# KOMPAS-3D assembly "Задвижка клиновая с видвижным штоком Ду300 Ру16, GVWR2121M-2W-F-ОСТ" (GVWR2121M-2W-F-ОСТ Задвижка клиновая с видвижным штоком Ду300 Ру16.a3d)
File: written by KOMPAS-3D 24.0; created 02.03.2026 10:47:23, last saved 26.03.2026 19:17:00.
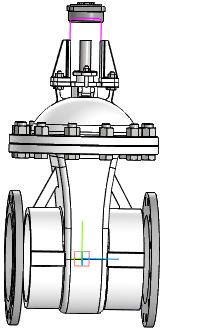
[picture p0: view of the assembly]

Document properties: Автор: R2D2; Полное имя файла: E:\Работа\Зайцев\GVWR2121M-2W-F-ОСТ Задвижка клиновая с видвижным штоком Ду50-300 Ру16\DN300\Исходные материалы\GVWR2121M-2W-F-ОСТ Задвижка клиновая с видвижным штоком Ду300 Ру16.a3d

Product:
- Component [detail]: AS 1110 - M10 x 35  | qty 4  | pos. 2  | Масса: 0.110391; Комментарий: Болты и винты   шестигранные точные   метрические ISO; Автор: R2D2; additional columns: Сталь, мягкая; source file: AS 1110 - M10 x 35 AS 1110 - M10 x 35.m3d
- Component [detail]: ANSI B18.2.4.2M - M10x1,5 - 16  | designation ANSI B18.2.4.2M - M10x1,5  | qty 4  | pos. 3  | Масса: 0.040912; Комментарий: Типы метрических   шестигранных гаек   2; Автор: R2D2; additional columns: Сталь, мягкая; source file: ANSI B18.2.4.2M - M10x1,5 ANSI B18.2.4.2M - M10x1,5 - 16.m3d
- Component [detail]: ANSI B18.2.4.2M - M8x1,25 - 13  | designation ANSI B18.2.4.2M - M8x1,25  | qty 1  | pos. 4  | Масса: 0.022147; Комментарий: Типы метрических   шестигранных гаек   2; Автор: R2D2; additional columns: Сталь, мягкая; source file: ANSI B18.2.4.2M - M8x1,25 ANSI B18.2.4.2M - M8x1,25 - 13.m3d
- Component [detail]: ANSI B18.2.4.2M - M20x2,5 - 30  | designation ANSI B18.2.4.2M - M20x2,5  | qty 12  | pos. 5  | Масса: 0.285661; Комментарий: Типы метрических   шестигранных гаек   2; Автор: R2D2; additional columns: Сталь, мягкая; source file: ANSI B18.2.4.2M - M20x2,5 ANSI B18.2.4.2M - M20x2,5 - 30.m3d
- Component [detail]: AS 1110 - M20 x 70  | qty 12  | pos. 6  | Масса: 0.838149; Комментарий: Болты и винты   шестигранные точные   метрические ISO; Автор: R2D2; additional columns: Сталь, мягкая; source file: AS 1110 - M20 x 70 AS 1110 - M20 x 70.m3d
- Component [detail]: Деталь1  | qty 1  | pos. 7  | Масса: 456.890978; Автор: R2D2; additional columns: Типовые; source file: 2.m3d
- Component [detail]: ANSI B18.2.4.2M - M8x1,25 - 13  | designation ANSI B18.2.4.2M - M8x1,25-01  | qty 1  | pos. 8  | Масса: 0.022147; Комментарий: Типы метрических   шестигранных гаек   2; Автор: R2D2; additional columns: Сталь, мягкая; source file: ANSI B18.2.4.2M - M8x1,25 ANSI B18.2.4.2M - M8x1,25 - 13.m3d
- Component [detail]: Фланец  | qty 2  | pos. 7  | Масса: 20.137324; Автор: R2D2; additional columns: Типовые; source file: Фланец DN300 Pn16 b31.m3d
- Component [assembly]: DN250_3D_STEP  | designation Сборка  | qty 1  | pos. 9  | Масса: 5.389074; Автор: R2D2; source file: Фланец Б.a3d
- Part/product: Задвижка клиновая с видвижным штоком Ду300 Ру16  | designation GVWR2121M-2W-F-ОСТ
    Масса: 210
    Раздел спецификации: Прочие изделия
    Примечание: D040-07880

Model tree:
1. Массив по концентрической сетке:1  (labels: Грань.Твердое тело1)  (12 pattern instances)
     Шаг 2 = 360
2. Массив по сетке:1  (labels: Грань.Твердое тело1)  (4 pattern instances)
     Шаг 1 = 50; Угол раствора = 90; Шаг 2 = 120
3. Масштабирование:1
4. Масштабирование : Твердое тело1
5. Масштабирование : Solid1  (labels: Твердое тело1; Solid1)
     Масштаб по оси Х = 1; Масштаб по оси Y = 1; Масштаб по оси Z = 1; Коэффициент = 1.5
6. Эскиз:1  (with: Вершина.Элемент выдавливания:2, Грань.Элемент вращения:1, Грань.Элемент выдавливания:5, Грань.Элемент выдавливания:7)  (labels: Грань.Твердое тело1; Грань.Solid1; Solid1; Твердое тело1)
     Ориентация = 2; Расстояние = -250; Ориентация = 2; Расстояние = -876

Referenced files in E:\Работа\Зайцев\GVWR2121M-2W-F-ОСТ Задвижка клиновая с видвижным штоком Ду50-300 Ру16\DN300\Исходные материалы\: AS 1110 - M10 x 35 AS 1110 - M10 x 35.m3d, ANSI B18.2.4.2M - M10x1,5 ANSI B18.2.4.2M - M10x1,5 - 16.m3d, ANSI B18.2.4.2M - M8x1,25 ANSI B18.2.4.2M - M8x1,25 - 13.m3d, ANSI B18.2.4.2M - M20x2,5 ANSI B18.2.4.2M - M20x2,5 - 30.m3d, AS 1110 - M20 x 70 AS 1110 - M20 x 70.m3d, 2.m3d, Фланец DN300 Pn16 b31.m3d, Фланец Б.a3d
Referenced files in E:\Работа\Зайцев\GVWR3131M-2W-F-S Задвижка клиновая с выдвижным штоком DN.ru Ду50-200 Ру63\DN200\исходные материалы\: ANSI B18.2.4.2M - M20x2,5 ANSI B18.2.4.2M - M20x2,5 - 30.m3d, AS 1110 - M20 x 70 AS 1110 - M20 x 70.m3d, ANSI B18.2.4.2M - M10x1,5 ANSI B18.2.4.2M - M10x1,5 - 16.m3d, AS 1110 - M10 x 35 AS 1110 - M10 x 35.m3d
Referenced files in E:\Работа\Зайцев\GVWR2626M-2W-F-S Задвижка клиновая с выдвижным штоком DN.ru Ду50-300 Ру16\DN300\исходные материалы\: Фланец DN300 Pn16 b31.m3d
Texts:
  Программные изделия  и базы данных
  ANSI B18.2.4.2M - M10x1,5
  ANSI B18.2.4.2M - M8x1,25
  ANSI B18.2.4.2M - M20x2,5
  ANSI B18.2.4.2M - M8x1,25 - 01
  ANSI B18.2.4.2M - M8x1,25-01
  GVWR2121M-2W-F-ОСТ
  AS 1110 - M10 x 35 AS 1110 - M10 x 35 (1)
  ANSI B18.2.4.2M - M10x1,5 ANSI B18.2.4.2M - M10x1,5 - 16 (1)
  ANSI B18.2.4.2M - M8x1,25 ANSI B18.2.4.2M - M8x1,25 - 13
  ANSI B18.2.4.2M - M20x2,5 ANSI B18.2.4.2M - M20x2,5 - 30 (1)
  AS 1110 - M20 x 70 AS 1110 - M20 x 70 (1)
  Деталь1 Деталь1
  ANSI B18.2.4.2M - M20x2,5 ANSI B18.2.4.2M - M20x2,5 - 30 (2)
  AS 1110 - M20 x 70 AS 1110 - M20 x 70 (2)
  ANSI B18.2.4.2M - M20x2,5 ANSI B18.2.4.2M - M20x2,5 - 30 (3)
  AS 1110 - M20 x 70 AS 1110 - M20 x 70 (3)
  ANSI B18.2.4.2M - M20x2,5 ANSI B18.2.4.2M - M20x2,5 - 30 (4)
  AS 1110 - M20 x 70 AS 1110 - M20 x 70 (4)
  ANSI B18.2.4.2M - M20x2,5 ANSI B18.2.4.2M - M20x2,5 - 30 (5)
  AS 1110 - M20 x 70 AS 1110 - M20 x 70 (5)
  ANSI B18.2.4.2M - M20x2,5 ANSI B18.2.4.2M - M20x2,5 - 30 (6)
  AS 1110 - M20 x 70 AS 1110 - M20 x 70 (6)
  ANSI B18.2.4.2M - M20x2,5 ANSI B18.2.4.2M - M20x2,5 - 30 (7)
  AS 1110 - M20 x 70 AS 1110 - M20 x 70 (7)
  ANSI B18.2.4.2M - M20x2,5 ANSI B18.2.4.2M - M20x2,5 - 30 (8)
  AS 1110 - M20 x 70 AS 1110 - M20 x 70 (8)
  ANSI B18.2.4.2M - M20x2,5 ANSI B18.2.4.2M - M20x2,5 - 30 (9)
  AS 1110 - M20 x 70 AS 1110 - M20 x 70 (9)
  ANSI B18.2.4.2M - M20x2,5 ANSI B18.2.4.2M - M20x2,5 - 30 (10)
  AS 1110 - M20 x 70 AS 1110 - M20 x 70 (10)
  ANSI B18.2.4.2M - M20x2,5 ANSI B18.2.4.2M - M20x2,5 - 30 (11)
  AS 1110 - M20 x 70 AS 1110 - M20 x 70 (11)
  ANSI B18.2.4.2M - M20x2,5 ANSI B18.2.4.2M - M20x2,5 - 30 (12)
  AS 1110 - M20 x 70 AS 1110 - M20 x 70 (12)
  ANSI B18.2.4.2M - M10x1,5 ANSI B18.2.4.2M - M10x1,5 - 16 (2)
  AS 1110 - M10 x 35 AS 1110 - M10 x 35 (2)
  ANSI B18.2.4.2M - M10x1,5 ANSI B18.2.4.2M - M10x1,5 - 16 (3)
  AS 1110 - M10 x 35 AS 1110 - M10 x 35 (3)
  ANSI B18.2.4.2M - M10x1,5 ANSI B18.2.4.2M - M10x1,5 - 16 (4)
  AS 1110 - M10 x 35 AS 1110 - M10 x 35 (4)
  ANSI B18.2.4.2M - M8x1,25-01 ANSI B18.2.4.2M - M8x1,25 - 13
  Фланец (1)
  Фланец (2)
  Сборка DN250_3D_STEP
  Ось Y.Начало координат
  Ось Z.Начало координат
  Плоскость ZY.Начало координат
  Плоскость ZX.Начало координат
  Плоскость XY.Начало координат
